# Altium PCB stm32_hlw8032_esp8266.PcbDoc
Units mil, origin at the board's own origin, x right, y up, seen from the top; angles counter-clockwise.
Board outline 3320.87 x 3460.63 mil, 2 copper layers (Top Layer, Bottom Layer); 68 components, 53 nets, 223 pads, 57 vias.
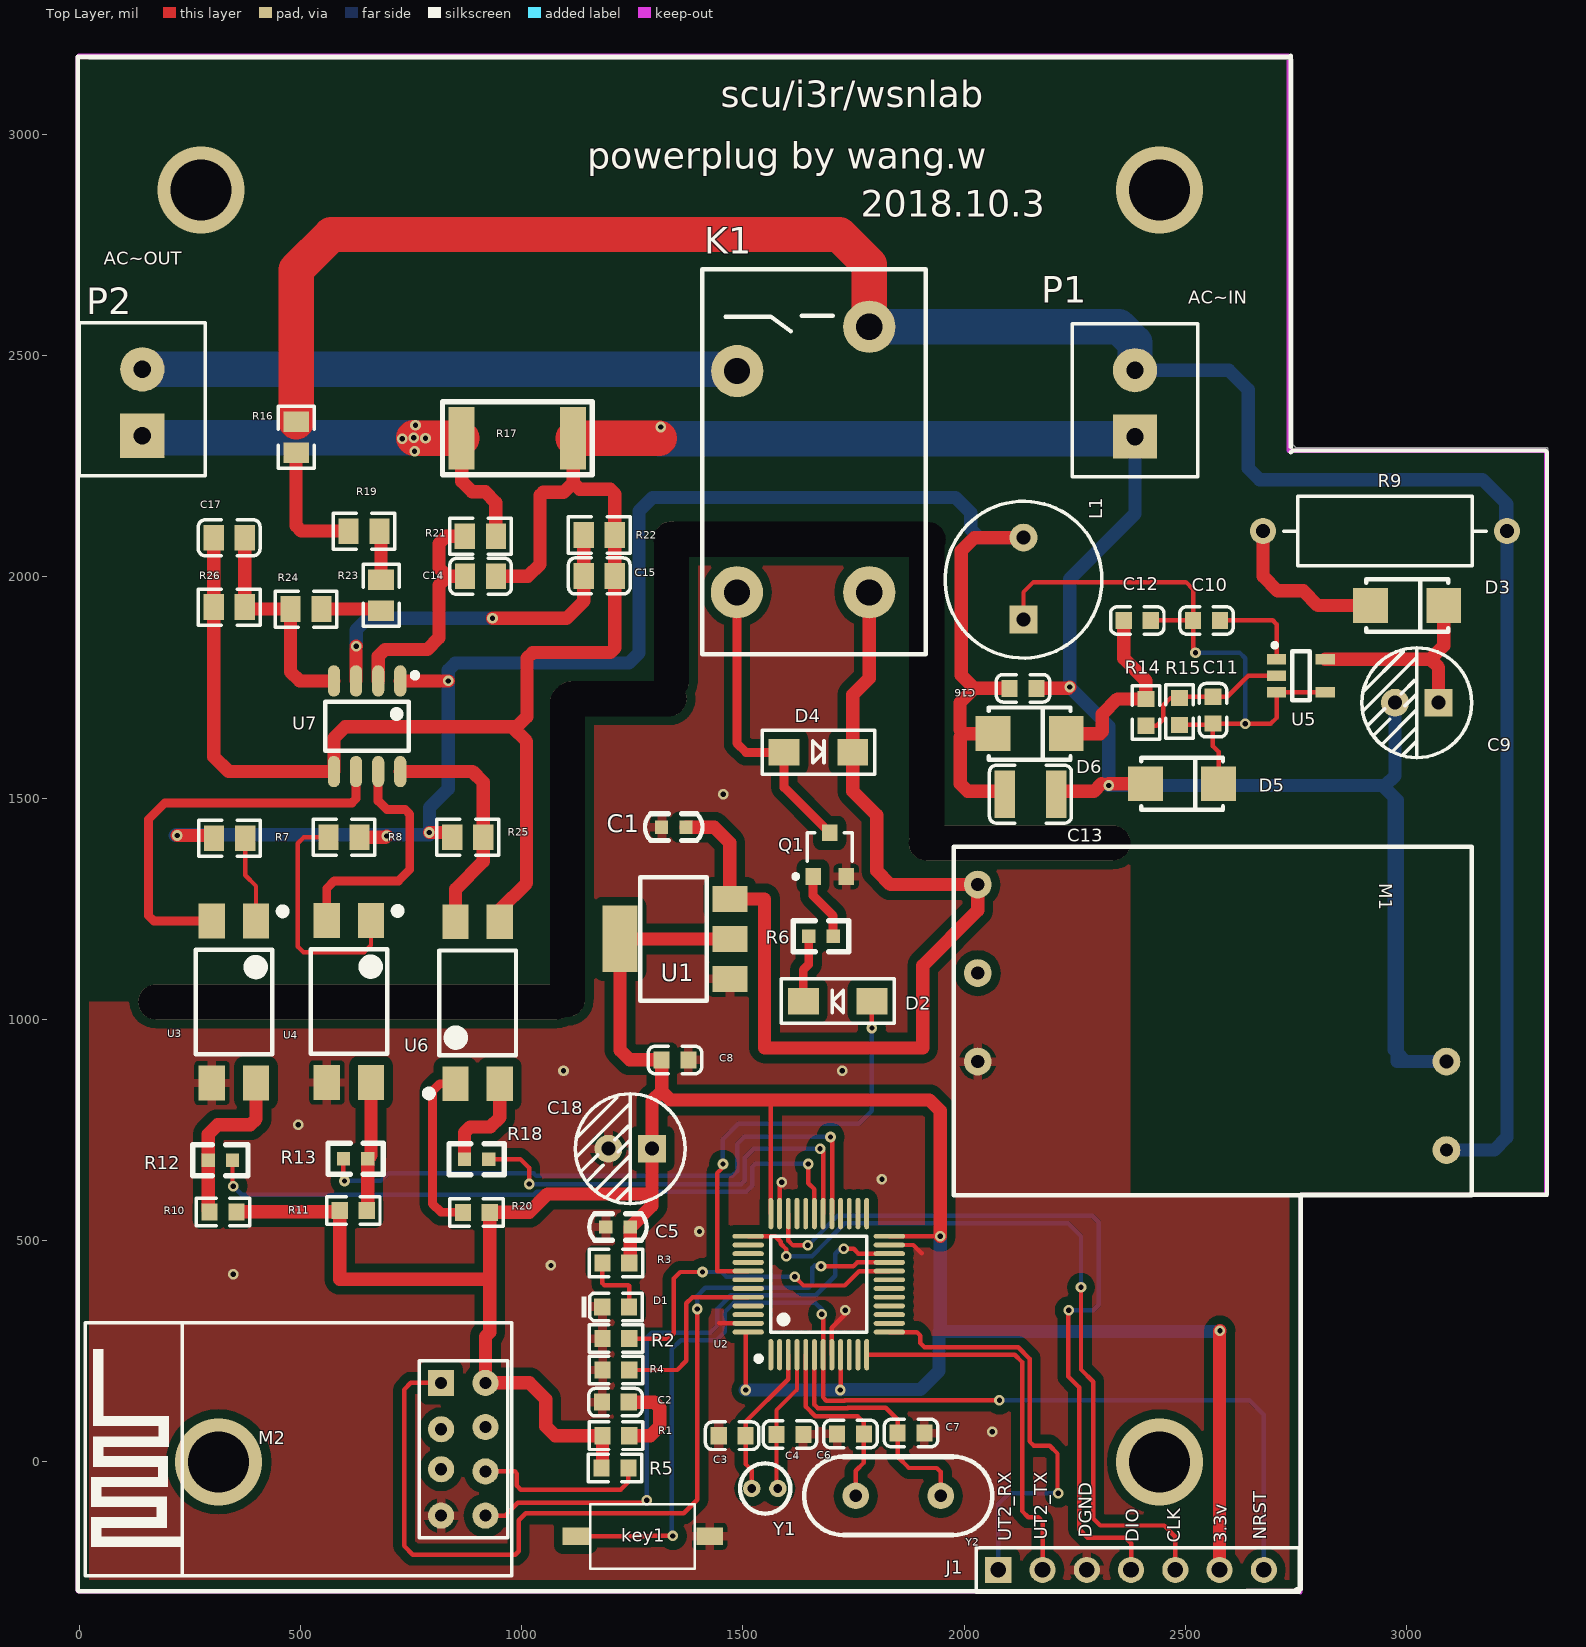
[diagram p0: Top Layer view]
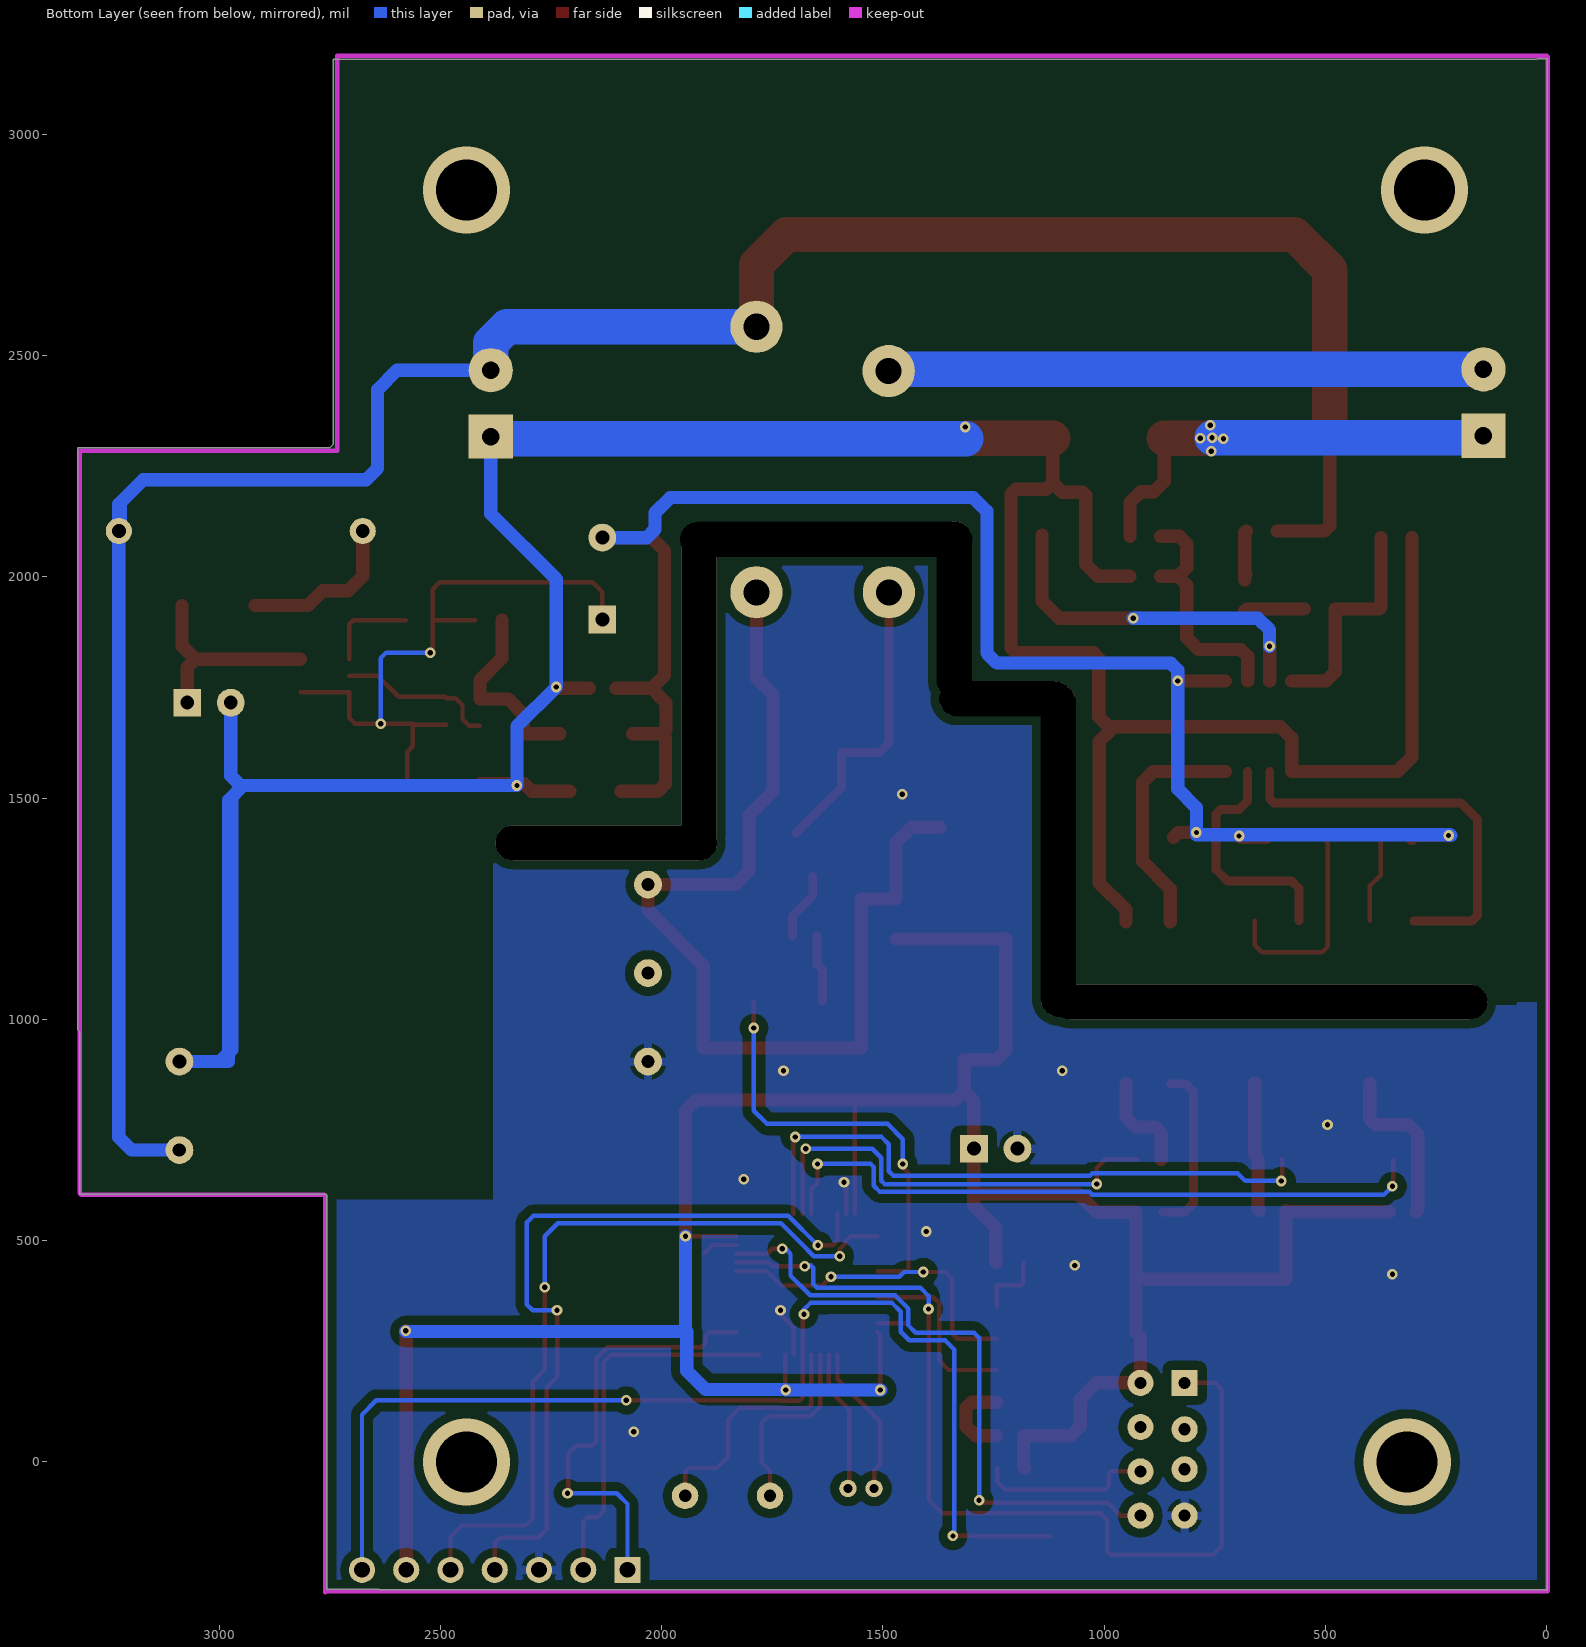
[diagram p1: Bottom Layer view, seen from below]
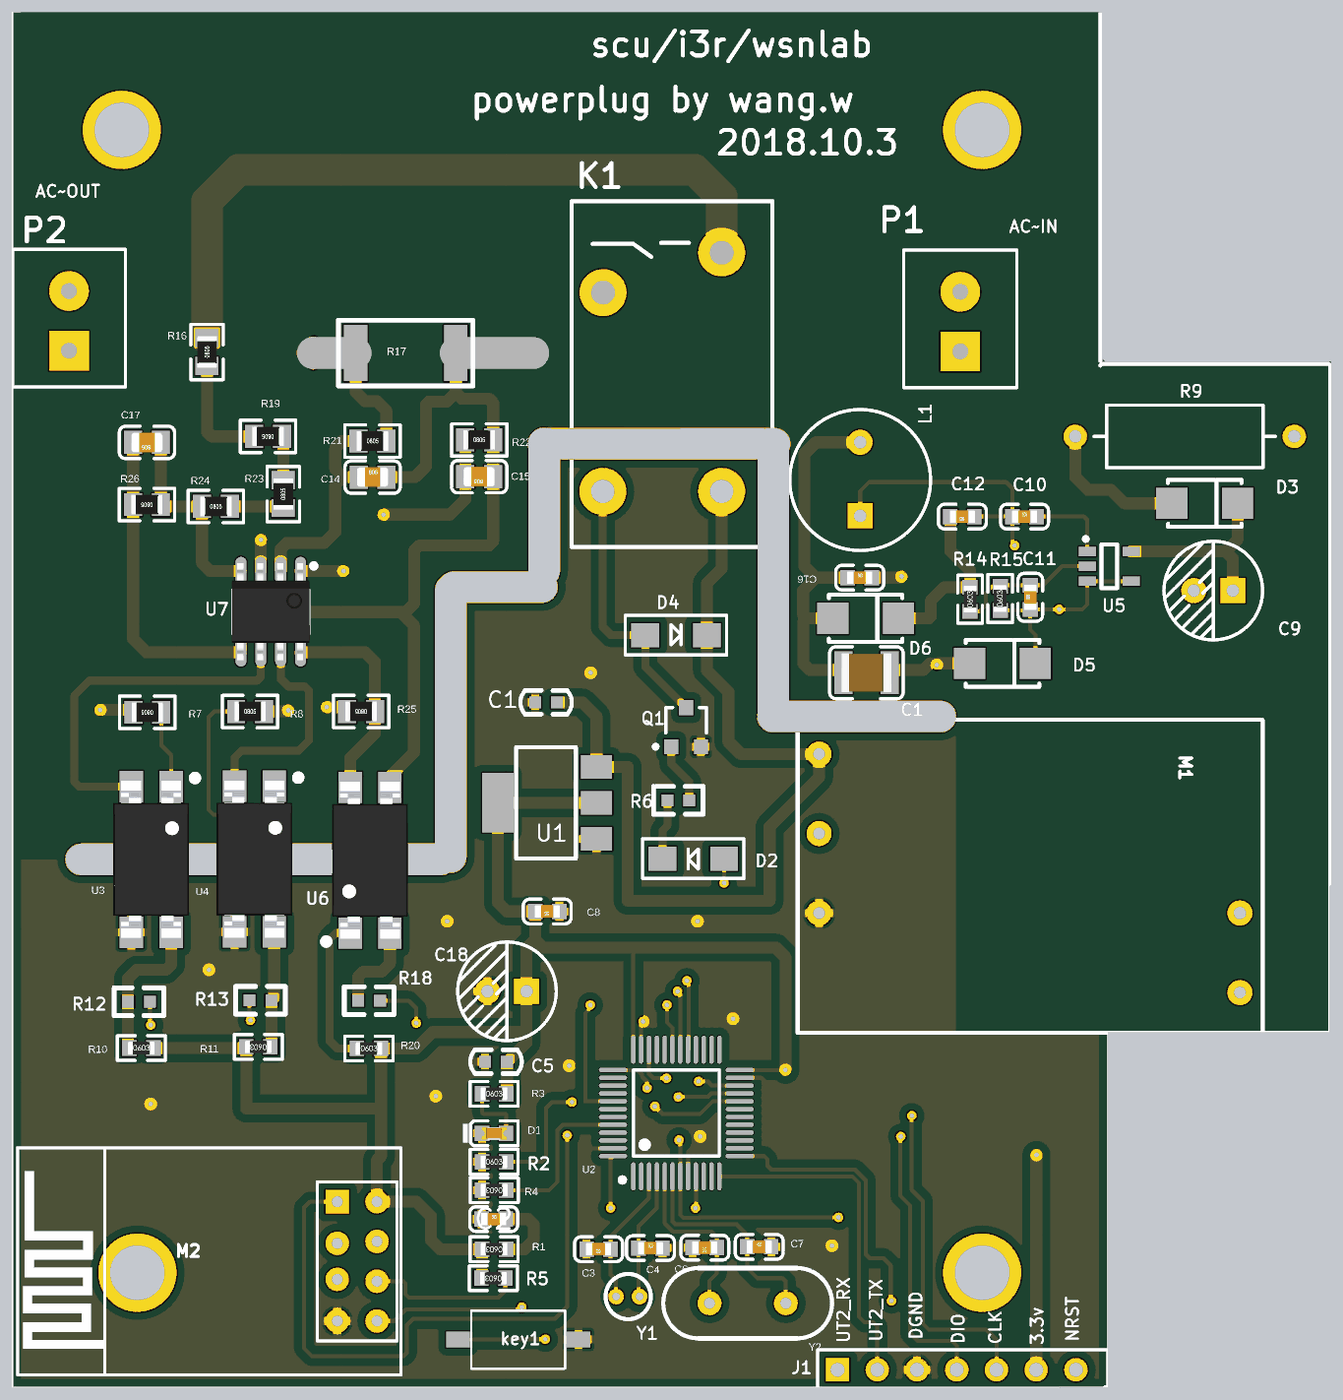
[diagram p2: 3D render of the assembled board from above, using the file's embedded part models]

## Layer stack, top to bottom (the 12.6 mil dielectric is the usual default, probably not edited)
Top Solder: solder mask 0.4, Solder Resist, Dk 3.5
Top Layer: signal copper 1.4
Dielectric 1: dielectric 12.6, FR-4, Dk 4.8
Bottom Layer: signal copper 1.4
Bottom Solder: solder mask 0.4, Solder Resist, Dk 3.5

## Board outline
22.64,3169.29 2742.13,3169.29 2742.13,2299.21 2750,2291.34 3318.9,2291.34 3318.9,976.38 3314.96,972.44 3314.96,604.33 2757.87,604.33 2756.89,603.35 2756.89,-288.39 2637.8,-288.39 2636.81,-289.37 -0.98,-289.37 -0.98,3170.28 -1.97,3171.26 20.67,3171.26

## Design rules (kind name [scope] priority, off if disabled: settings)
Clearance Clearance_1 [InPolygon] p1: gap=20 ignorepadtopadclearanceinfootprint=FALSE except(0: Arc-Hole Track-Hole SMDPad-Hole THPad-Hole Via-Hole Fill-Hole Poly-Hole Region-Hole Text-Hole)
Clearance [All] p2: gap=7 ignorepadtopadclearanceinfootprint=FALSE except(0: Arc-Hole Track-Hole SMDPad-Hole THPad-Hole Via-Hole Fill-Hole Poly-Hole Region-Hole Text-Hole)
ComponentClearance [All] p1: gap=4 collisioncheckmode=3 verticalgap=4 showdistances=FALSE
DiffPairsRouting [All] p1: maxlimit=10 minlimit=10 mostfreqgap=10 toplayer_minwidth=10 toplayer_maxwidth=15 toplayer_prefwidth=15 bottomlayer_minwidth=10 bottomlayer_maxwidth=15 bottomlayer_prefwidth=15 maxuncoupledlength=500
HoleSize [All] p1: absolutevalues=TRUE maxlimit=500 minlimit=1 maxpercent=80.000 minpercent=20.000
HoleToHoleClearance [All] p1: gap=4 allowstackedmicrovias=TRUE
MinimumSolderMaskSliver [All] p1: minsoldermaskwidth=4
PolygonConnect PolygonConnect_1 [Isvia] p1: connectstyle=Direct reliefconductorwidth=10 reliefentries=4 polygonreliefangle="90 Angle" airgapwidth=10
PolygonConnect [All] p2: connectstyle=Relief reliefconductorwidth=20 reliefentries=4 polygonreliefangle="90 Angle" airgapwidth=10
RoutingVias [All] p1: holewidth=20 width=30 viastyle="Through Hole" minholewidth=10 minwidth=10 maxholewidth=28 maxwidth=50
SilkToSilkClearance [All] p1: silktosilkclearance=4
SilkToSolderMaskClearance [IsPad] p1: minsilkscreentomaskgap=0 clearancetoexposedcopper=TRUE
SolderMaskExpansion [All] p1: expansion=4
Width [All] p1: maxlimit=500 minlimit=10 preferedwidth=10 minimp=50.000000 maximp=50.000000 favimp=50.000000
23 further rules are at their usual default settings.

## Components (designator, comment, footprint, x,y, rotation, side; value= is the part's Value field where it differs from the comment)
C1 "104" 0603C 1349.41,1433.07 r0 top
C2 "0.1μF" LC-0603_C 1211.61,134.84 r0 top
C3 "6pF" LC-0603_C 1475.59,59.06 r180 top
C4 "6pF" LC-0603_C 1606.1,62.01 r0 top
C5 "104" 0603C 1223.43,529.53 r0 top
C6 "20pF" LC-0603_C 1742.91,62.99 r180 top
C7 "20pF" LC-0603_C 1879.72,64.96 r0 top
C8 "0.1μF" LC-0603_C 1346.46,908.46 r180 top
C9 "3.3μF/400V" CAP-ELECT-TH-6.3X7 3022.64,1715.55 r180 top value=2.2μF/400V
C10 "2.2μF/10V" LC-0603_C 2547.44,1901.57 r0 top value="100nF (104) ±10% 50V"
C11 "470pF" LC-0603_C 2562.01,1698.62 r90 top value="100nF (104) ±10% 50V"
C12 "220nF" LC-0603_C 2390.94,1901.57 r180 top value="100nF (104) ±10% 50V"
C13 "100μF" LC-1210_C 2149.61,1508.86 r180 top value="100nF (104) ±10% 50V"
C14 "33nF" LC-0805_C 906.89,2000.98 r0 top value="100nF (104) ±10% 50V"
C15 "33nF" LC-0805_C 1175.2,2001.97 r180 top value="100nF (104) ±10% 50V"
C16 "0.1μF" LC-0603_C 2132.87,1748.03 r0 top value="100nF (104) ±10% 50V"
C17 "33nF" LC-0805_C 338.98,2088.19 r180 top value="100nF (104) ±10% 50V"
C18 "1000μF/400V" CAP-ELECT-TH-6.3X7 1245.08,707.68 r180 top value=2.2μF/400V
D1 "POWER" LC-0603_LED_S1 1212.4,350.39 r0 top value=红色
D2 "IN4148" 1206D 1841.34,1071.34 r270 top
D3 "1N4007" LC-SMA(DO-214AC)_S1 3000.98,1935.04 r180 top
D4 "" 1206D 1543.03,1573.35 r90 top
D5 "US1J(600V 1A)" LC-SMA(DO-214AC)_S1 2492.13,1532.48 r180 top
D6 "1N4007" LC-SMA(DO-214AC)_S1 2147.64,1645.67 r180 top
J1 "4P/NC" HDR1X7 2076.97,-244.09 r0 top
K1 "Relay-5V" SJ-S-105LMH 1683.07,1964.96 r90 top
key1 "SW" KEY-2 1424.61,-168.33 r180 top
L1 "1mH" L-10X14 2133.86,1993.54 r90 top
M1 "ACDC_THX208based" ACDC_THX208 3146.65,605.31 r180 top
M2 "ESP-01&01S Module" "ESP-01&01S Module" 867.91,28.54 r90 top
P1 "Header" 3.81-2P 2386.81,2316.93 r90 top
P2 "Header" 3.81-2P 143.7,2318.9 r90 top
Q1 "S8050" SOT-23 1695.86,1372.05 r0 top
R1 "10KΩ" LC-0603_R 1212.6,59.06 r180 top
R2 "10KΩ" LC-0603_R 1212.6,278.54 r0 top
R3 "1.5KΩ" LC-0603_R 1212.6,449.8 r0 top
R4 "10KΩ" LC-0603_R 1212.8,207.68 r180 top
R5 "4.7KΩ" LC-0603_R 1210.83,-13.78 r180 top
R6 "Res2" 0603 1703.74,1187.99 r180 top value=4.7K
R7 "1KΩ,1%" LC-0805_R 339.96,1409.45 r180 top
R8 "1KΩ,1%" LC-0805_R 598.43,1411.42 r0 top
R9 "39Ω/1W" R-1W-THT 2950.79,2103.35 r180 top
R10 "2.2KΩ" LC-0603_R 325,564.96 r0 top
R11 "2.2KΩ" LC-0603_R 619.29,567.91 r180 top
R12 "0Ω/1W" 0603 291.34,681.5 r0 top
R13 "0Ω/1W" 0603 652.17,685.04 r180 top
R14 "5.49KΩ" LC-0603_R 2410.43,1693.7 r90 top
R15 "4.99KΩ" LC-0603_R 2486.22,1695.67 r90 top
R16 "470KΩ,1%" LC-0805_R 490.16,2315.55 r90 top
R17 "2mΩ/25A" R2512 990.16,2312.99 r0 top
R18 "0Ω/1W" 0603 925.47,684.06 r180 top
R19 "470KΩ,1%" LC-0805_R 643.7,2103.35 r180 top
R20 "2.2KΩ" LC-0603_R 897.64,563.98 r0 top
R21 "1KΩ,1%" LC-0805_R 906.5,2091.54 r0 top
R22 "1KΩ,1%" LC-0805_R 1175.2,2094.49 r0 top
R23 "470KΩ,1%" LC-0805_R 682.09,1958.27 r90 top
R24 "470KΩ,1%" LC-0805_R 512.4,1927.17 r0 top
R25 "1KΩ,1%" LC-0805_R 877.95,1411.42 r180 top
R26 "1KΩ,1%" LC-0805_R 338.98,1931.69 r180 top
U1 "LM1117-3.3V" SOT-223/P2.3 1359.25,1180.12 r180 top
U2 "STM32F103C8T6" LC-LQFP-48_7x7x05P 1671.26,401.57 r0 top
U3 "PC817" LC-SMD-4 349.61,1039.37 r270 top
U4 "PC817" LC-SMD-4 609.45,1040.35 r270 top
U5 "MP150" LC-SOT-23-5 2760.83,1776.58 r180 top
U6 "PC817" LC-SMD-4 900.39,1037.4 r90 top
U7 "HLW8032" LC-SOP-8_150mil 650.59,1662.4 r180 top
Y1 "32.768K" CRYSTAL 1528.74,-60.04 r180 top
Y2 "8M" 49/U_N 1754.85,-76.77 r0 top value="25MHz ±20ppm 20pF"

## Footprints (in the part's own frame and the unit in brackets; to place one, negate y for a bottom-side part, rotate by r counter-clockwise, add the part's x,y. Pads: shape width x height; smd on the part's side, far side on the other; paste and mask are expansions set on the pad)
3.81-2P [mil]
  rect 100x100 hole 39.37: 1(0,0.99)
  round 100 hole 39.37: 2(150,1)
  silkscreen extent -91,-141 255,143
49/U_N [mil]
  round 60 hole 28: 1(0,0) 2(192,0)
  silkscreen extent -116,-88 308,89, body extent -117,-88 309,89, height 512
0603 [mil]
  rect 30x30 smd: 1(0,0) 2(55,0)
  silkscreen extent -35,-35 90,35
0603C [mil]
  rect 30x30 smd: 1(21.61,1.26) 2(-33.39,1.26)
  silkscreen extent -71,-29 59,31
1206D [mil]
  rect 60x70 smd: 1(30,-50) 2(30,-205)
  silkscreen extent -20,-255 80,0
ACDC_THX208 [mm]
  round 1.6 hole 0.762: 1(1.45,-2.52) 3(28.35,-7.6) 4(28.35,-12.68) 5(28.35,-17.76)
  round 1.6 hole 0.8: 2(1.45,-7.6)
  silkscreen extent 0,-19.94 29.72,0.06
CAP-ELECT-TH-6.3X7 [mm]
  rect 1.6x1.6 hole 0.8: 1(-1.25,0)
  round 1.6 hole 0.8: 2(1.25,0)
  silkscreen extent -3.15,-3.15 3.15,3.15
CRYSTAL [mm]
  round 1 hole 0.5: 1(-1.27,0) 2(0.23,0)
  silkscreen extent -1.99,-1.44 0.9,1.44
"ESP-01&01S Module" [mm]
  rect 1.5x1.5 hole 0.7: 1(3.81,1.27)
  round 1.5 hole 0.7: 2(1.15,1.27) 3(-1.15,1.27) 4(-3.81,1.27) 5(3.81,-1.27) 6(1.27,-1.27) 7(-1.27,-1.27) 8(-3.81,-1.27)
  silkscreen extent -7.25,-2.79 7.25,21.71
HDR1X7 [mm]
  rect 1.5x1.5 hole 0.9: 1(0,0)
  round 1.5 hole 0.9: 2(2.54,0) 3(5.08,0) 4(7.62,0) 5(10.16,0) 6(12.7,0) 7(15.24,0)
  silkscreen extent -1.27,-1.27 17.27,1.27
KEY-2 [mm]
  rect 1.5x1 smd: 1(-0.005,-0.001) 2(7.685,-0.001)
  silkscreen extent 0.85,-1.85 6.85,1.86
L-10X14 [mm]
  rect 1.6x1.6 hole 0.8: 1(-2.286,0)
  round 1.6 hole 0.8: 2(2.413,0)
  silkscreen extent -4.5,-4.5 4.5,4.5
LC-0603_C [mm]
  rect 0.93x0.98 smd: 1(-0.77,0) 2(0.77,0)
  silkscreen extent -1.53,-0.79 1.54,0.79, body extent -0.8,-0.4 0.8,0.4, height 0.3
LC-0603_LED_S1 [mm]
  rect 0.93x0.98 smd: A(0.77,0) K(-0.77,0)
  silkscreen extent -1.98,-0.79 1.53,0.79, body extent -0.8,-0.4 0.8,0.4, height 0.6
LC-0603_R [mm]
  rect 0.93x0.98 smd: 1(-0.77,0) 2(0.77,0)
  silkscreen extent -1.54,-0.79 1.53,0.79, body extent -0.85,-0.4 0.85,0.4, height 0.56
LC-0805_C [mm]
  rect 1.16x1.47 smd: 1(-0.89,0) 2(0.89,0)
  silkscreen extent -1.77,-1.04 1.77,1.04, body extent -1,-0.62 1,0.63, height 0.77
LC-0805_R [mm]
  rect 1.16x1.47 smd: 1(-0.89,0) 2(0.89,0)
  silkscreen extent -1.77,-1.03 1.77,1.04, body extent -1,-0.62 1,0.63, height 0.49
LC-1210_C [mm]
  rect 1.16x2.72 smd: 1(-1.475,0) 2(1.475,0)
  silkscreen extent -2.36,-1.66 2.35,1.66, body extent -1.6,-1.25 1.6,1.25, height 1.3
LC-LQFP-48_7x7x05P [mm]
  oval 0.28x1.8 smd mask+0.051: 1(-2.75,-4.05) 2(-2.25,-4.05) 3(-1.75,-4.05) 4(-1.25,-4.05) 5(-0.75,-4.05) 6(-0.25,-4.05) 7(0.25,-4.05) 8(0.75,-4.05) 9(1.25,-4.05) 10(1.75,-4.05) 11(2.25,-4.05) 12(2.75,-4.05) 25(2.75,4.05) 26(2.25,4.05) 27(1.75,4.05) 28(1.25,4.05) 29(0.75,4.05) 30(0.25,4.05) 31(-0.25,4.05) 32(-0.75,4.05) 33(-1.25,4.05) 34(-1.75,4.05) 35(-2.25,4.05) 36(-2.75,4.05)
  oval 1.8x0.28 smd mask+0.051: 13(4.05,-2.75) 14(4.05,-2.25) 15(4.05,-1.75) 16(4.05,-1.25) 17(4.05,-0.75) 18(4.05,-0.25) 19(4.05,0.25) 20(4.05,0.75) 21(4.05,1.25) 22(4.05,1.75) 23(4.05,2.25) 24(4.05,2.75) 37(-4.05,2.75) 38(-4.05,2.25) 39(-4.05,1.75) 40(-4.05,1.25) 41(-4.05,0.75) 42(-4.05,0.25) 43(-4.05,-0.25) 44(-4.05,-0.75) 45(-4.05,-1.25) 46(-4.05,-1.75) 47(-4.05,-2.25) 48(-4.05,-2.75)
  silkscreen extent -3.6,-4.42 2.75,2.75
LC-SMA(DO-214AC)_S1 [mm]
  rect 2x2 smd: 1(2.1,0) 2(-2.1,0)
  silkscreen extent -2.35,-1.5 2.35,1.5
LC-SMD-4 [mm]
  rect 2x1.5 smd: 1(-4.65,1.27) 2(-4.65,-1.27) 3(4.65,-1.27) 4(4.65,1.27)
  silkscreen extent -5.4,-2.2 3,3, body extent -5.02,-2.42 5.01,2.42, height 3.9
LC-SOP-8_150mil [mm]
  oval 0.7x1.8 smd: 1(-1.905,-2.6) 2(-0.635,-2.6) 3(0.635,-2.6) 4(1.905,-2.6) 5(1.905,2.6) 6(0.635,2.6) 7(-0.635,2.6) 8(-1.905,2.6)
  silkscreen extent -2.9,-3.07 2.4,1.4, body extent -2.5,-3.1 2.5,3.1, height 1.75
LC-SOT-23-5 [mm]
  rect 1.1x0.6 smd: 1(1.4,-0.95) 2(1.4,0) 3(1.4,0.95) 4(-1.4,0.95) 5(-1.4,-0.95)
  silkscreen extent -0.5,-1.87 1.62,1.4
R2512 [mm]
  rect 1.5x3.6 smd: 1(-3.2,0) 2(3.2,0)
  silkscreen extent -4.3,-2.1 4.3,2.1
R-1W-THT [mm]
  round 1.5 / inner oval 1.5x2 / far side round 1.5 hole 0.8: 1(-7,0)
  round 1.5 hole 0.8: 2(7,0)
  silkscreen extent -5.8,-2 5.8,2
SJ-S-105LMH [mm]
  round 3 hole 1.5: 1(0,5) 2(0,-2.6) 3(12.7,4.984) 4(15.24,-2.6)
  silkscreen extent -3.56,-5.84 18.54,6.98
SOT-23 [mm]
  rect 0.9x0.95 smd: 1(-0.95,-1.25) 2(0.95,-1.25) 3(0,1.25)
  silkscreen extent -2.07,-1.37 1.3,1.25
SOT-223/P2.3 [mil]
  rect 79x59 smd: 1(-111,89.1) 2(-111,-1.45) 3(-111,-92)
  rect 79x150 smd: 2(137,-1.9)
  silkscreen extent -59,-141 91,139

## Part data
C1 C5: library part CAP, "Capacitor"
C2 C3 C4 C6 C7 C8: library part Cap, "贴片电容"
C9 C18: library part "Cap Pol1", "直插电解电容"
C10 C11 C12 C13 C14 C15 C16 C17: library part CAP, "贴片电容"
D1: library part LED1, "发光二极管"
D2 D4: library part Diode, "Default Diode", PackageDocument=Sep-1996
D3 D5 D6: library part "Diode 1N5408", "贴片二极管"
J1: library part "Header 7", "接口"
K1: library part SJ-S-105LMH, "Single-Pole Dual-Throw Relay"
key1: "Switch"
L1: library part IND_8, "直插绕线电感"
M1: library part ACDC, "THX208Based"
P1 P2: library part "Header 2", "Header, 2-Pin"
Q1: library part NPN, "NPN Bipolar Transistor"
R1 R2 R3 R4 R7 R8 R9 R10 R11 R12 R13 R14 R15 R16 R17 R18 R19 R20 R21 R22 R23 R24 R25 R26: library part 电阻, "贴片电阻"
R5: library part "0805 62KΩ (6202) 1%", "贴片电阻", Package=0402, SuppliersPartNumber=C17783
R6: "Resistor"
U1: library part 1117
U2: library part STM32F103CBT6, "IC"
U3 U4 U6: library part PS2501L-1-F3-A, "IC"
U5 U7: "IC"
Y1: library part XTAL, "Crystal Oscillator"
Y2: library part XTAL_1, "晶振（直插）"

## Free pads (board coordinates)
  oval 984.25x78.74 hole 78.74 slot 984.25 at 0 deg paste+0: 0(625.98,1039.37)
  oval 78.74x750 hole 78.74 slot 750 at 90 deg paste+0: 0(1103.35,1380.91) 0(1915.35,1748.03)
  oval 300x78.74 hole 78.74 slot 300 at 0 deg paste+0: 0(1222.44,1724.41)
  oval 78.74x400 hole 78.74 slot 400 at 90 deg paste+0: 0(1338.58,1925.2)
  oval 600x78.74 hole 78.74 slot 660 at 0 deg paste+0: 0(1627.95,2084.65)
  oval 500x78.74 hole 78.74 slot 500 at 0 deg paste+0: 0(2125,1398.62)

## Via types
v1: diameter 24, hole 12, Top Layer to Bottom Layer, 53 vias
v2: diameter 196.85, hole 137.8, Top Layer to Bottom Layer, 4 vias

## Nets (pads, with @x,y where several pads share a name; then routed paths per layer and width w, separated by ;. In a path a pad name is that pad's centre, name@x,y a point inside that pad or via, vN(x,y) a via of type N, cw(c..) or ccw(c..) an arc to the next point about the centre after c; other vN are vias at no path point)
+3.3V: C5.1 C8.2 C18.1 J1.6 M2.5 R1.2 R3.2 R5.2 R10.2 R11.2 R20.2 U1.2 U2.9 U2.24 U2.36 U2.48 | length 6476.4
  Top Layer w10: v1(1505.91,162.4) 1505.91,287.4 U2.48 ; U2.36 1562.99,813.98 1566.93,817.91 ; v1(1719.49,162.4) 1720.47,163.38 U2.9 ; U2.24 v1(1945.87,509.84)
  Top Layer w30: R10.2 586.02,564.96 R11.2 588.98,412.99 927.56,412.99 927.95,413.39 ; R5.2@1178.54,-14.76 1182.28,-11.02 R1.2 1075.79,59.06 1054.13,80.71 1054.13,141.73 1017.32,178.54 M2.5 917.91,283.07 927.95,293.11 927.95,413.39 ; R3.2 1245.04,451.93 C5.1 1246.33,530.79 1294.29,578.74 1294.29,610.24 ; U1.2@1470.25,1181.57 1222.7,1181.57 1222.25,1182.02 1222.25,930.31 1244.09,908.47 C8.2 1316.14,837.4 ; v1(1945.87,509.84) 1945.87,793.31 1921.26,817.91 1566.93,817.91 1335.63,817.91 1316.14,837.4 ; J1.6 2576.97,295.47 v1(2577.76,296.26) ; 927.95,413.39 R20.2 1016.73,563.98 1058.07,605.32 1289.37,605.32 1294.29,610.24 ; 1294.29,610.24 C18.1 1294.29,815.55 1316.14,837.4
  Bottom Layer w30: v1@1504.92,162.4 v1(1505.91,162.4) v1(1719.49,162.4) ; v1@1719.49,163.39 1900.59,163.39 1943.11,205.91 1943.11,294.49 ; v1(1945.87,509.84) 1945.87,297.24 1943.11,294.49 ; v1@2577.76,294.49 1943.11,294.49
+5V: C1.1 D4.2 K1.2 M1.5 U1.3 | length 2342.1
  Top Layer w30: C1.1 1434.76,1434.33 1470.25,1398.84 U1.3 1548.75,1272.12 1548.75,935.5 1905.96,935.5 1905.96,1121.6 2030.51,1246.15 M1.5 1833.27,1304.53 1802.17,1335.63 1802.17,1461.61 1748.03,1515.75 D4.2 1748.03,1733.27 1785.43,1770.67 K1.2
A+5V: C13.2 C16.1 D6.1 L1.2 R7.2 R8.2 R25.2 U7.1 | length 3957.2
  Top Layer w30: v1(221.46,1415.35) 299.02,1415.35 R7.2 ; R8.2 691.93,1411.42 v1(694.88,1414.37) ; U7.1 v1(833.66,1764.76) ; v1(791.34,1422.24) 832.09,1422.24 R25.2 ; D6.1 1999.01,1645.67 ; C13.2@2091.54,1515.75 2007.87,1515.75 1991.14,1532.48 1991.14,1637.8 1999.01,1645.67 ; C16.1 2022.64,1748.03 ; L1.2 2022.6,2088.54 1993.11,2059.06 1993.11,1777.56 2022.64,1748.03 ; 1999.01,1645.67 1990.16,1654.53 1990.16,1715.55 2022.64,1748.03
  Bottom Layer w30: v1(221.46,1415.35) 216.54,1415.35 218.5,1417.32 791.34,1417.32 v1(791.34,1422.24) 791.34,1478.35 833.66,1520.67 v1(833.66,1764.76) 833.66,1789.37 849.41,1805.12 1242.13,1805.12 1264.76,1827.76 1264.76,2148.62 1295.28,2179.13 1980.31,2179.13 2014.76,2144.69 2014.76,2107.28 2033.5,2088.54 L1.2
AC220V-L: K1.4 M1.1 P1.2 R9.1 R16.2 | length 5241.5
  Top Layer w80: R16.2 490.16,2693.9 569.88,2773.62 1717.52,2773.62 1785.43,2705.71 K1.4
  Bottom Layer w30: P1.2 2598.03,2466.93 2641.73,2423.23 2641.73,2245.08 2667.32,2219.49 3171.26,2219.49 3223.42,2167.32 ; M1.1 3197.64,704.53 3226.38,733.27 R9.1 3226.38,2164.37 3223.42,2167.32 ; R9.1@3223.42,2093.5 3223.42,2167.32
  Bottom Layer w80: K1.4 2349.41,2564.96 2385.81,2528.56 P1.2
AC220V-N: C9.2 C13.1 C14.2 C15.1 C16.2 C17.2 D5.1 M1.2 P1.1 R17.2 R22.2 R26.2 U6.3 U7.5 | length 7627.9
  Top Layer w30: C17.2 R26.2 303.94,1593.7 337.6,1560.04 U7.5 575.59,1635.63 601.38,1661.42 977.36,1661.42 ; C14.2 1013.78,2000.98 1041.34,2028.54 1041.34,2184.06 1048.23,2190.94 1094.49,2190.94 1116.14,2212.6 ; U6.3 950.39,1247.64 1010.83,1308.07 1010.83,1627.95 977.36,1661.42 ; R17.2 1116.14,2212.6 ; C16.2 2235.24,1748.03 v1(2238.19,1750.98) ; C13.1@2207.68,1515.75 2293.31,1515.75 2310.04,1532.48 ; v1@2326.77,1532.48 D5.1 ; 977.36,1661.42 989.17,1661.42 1011.81,1684.06 1011.81,1815.94 1024.61,1828.74 1200,1828.74 1210.24,1838.98 C15.1 R22.2 1210.24,2187.4 1199.8,2197.83 1130.91,2197.83 1116.14,2212.6
  Top Layer w80: R17.2 1311.02,2312.99
  Bottom Layer w30: P1.1 2385.83,2142.72 2238.19,1995.08 v1(2238.19,1750.98) 2326.77,1662.4 v1(2326.77,1528.54) 2944.88,1528.54 2978.35,1495.08 2978.35,924.21 ; 2951.77,1528.54 2973.42,1550.19 C9.2 ; 2971.45,1495.08 2971.45,931.11 2978.35,924.21 ; M1.2 2998.03,904.53 ; 2978.35,924.21 2978.35,904.53 2998.03,904.53 ; 2978.35,924.21 2998.03,904.53
  Bottom Layer w80: 1312.01,2312.01 2380.9,2312.01 P1.1
  other v1: 1313.98,2338.58
BOOT0: R4.1 U2.44 | length 412.9
  Top Layer w10: R4.1 1351.38,207.68 1372.05,228.35 1372.05,358.27 1385.83,372.05 U2.44
CTL_Pin: D2.1 U2.41 | length 984.6
  Top Layer w10: v1(1454.72,673.23) 1454.72,665.35 1441.93,652.56 1441.93,431.1 U2.41 ; v1(1791.34,980.32) D2.1
  Bottom Layer w10: v1(1454.72,673.23) 1454.72,729.33 1489.17,763.78 1761.81,763.78 1791.34,793.31 v1(1791.34,980.32)
DGND: C1.2 C2.1 C3.2 C4.2 C5.2 C6.2 C7.2 C8.1 C18.2 D1.K J1.3 key1.1 M1.3 M2.4 Q1.2 R2.1 R4.2 U1.1 U2.8 U2.23 U2.35 U2.47 U3.3 U4.3 | length 332.5
  Top Layer w10: 1445.86,312.99 U2.47 ; U2.35 1582.68,626.97 v1(1587.6,631.89) ; U2.8 1700.79,303.15 1731.3,333.66 v1(1731.3,342.52) ; U2.23 1884.84,490.16 1903.54,471.46
  other v1: 2062.99,67.91 348.43,424.21 1065.94,443.9 1401.57,520.67 1813.98,638.78 495.08,761.81 1094.49,883.86 1724.41,883.86 1455.71,1508.86
NetC2_2: C2.2 R1.1 | length 194.8
  Top Layer w30: C2.2 1299.21,134.84 1312.01,122.05 1312.01,80.71 1290.35,59.06 R1.1
NetC9_1: C9.1 D3.2 U5.5 | length 482.6
  Top Layer w30: U5.5 3053.15,1813.98 ; C9.1@3075.78,1711.61 C9.1 3071.85,1795.28 3053.15,1813.98 ; D3.2 3083.66,1844.49 3053.15,1813.98
NetC10_1: C10.1 C11.1 C12.1 D5.2 L1.1 R15.1 U5.3 U5.4 | length 1503.4
  Top Layer w10: L1.1 2133.86,1965.55 2156.5,1988.19 2500.98,1988.19 2517.13,1972.05 C10.1 ; C12.1 C10.1 ; R15.1 2559.06,1665.35 C11.1 ; v1(2522.64,1828.74) 2517.13,1834.25 C10.1 ; D5.2 2574.8,1604.33 2562.01,1617.13 C11.1 ; U5.4 U5.3 2705.71,1681.1 2692.91,1668.31 v1(2634.84,1668.31) C11.1
  Bottom Layer w10: v1(2522.64,1828.74) 2622.05,1828.74 2634.84,1815.94 v1(2634.84,1668.31)
NetC10_2: C10.2 U5.1 | length 210.4
  Top Layer w10: C10.2 2696.85,1901.57 2705.71,1892.72 U5.1
NetC11_2: C11.2 R14.1 R15.2 U5.2 | length 360.6
  Top Layer w10: R14.1 2435.04,1663.39 2449.8,1678.15 2449.8,1709.65 2466.14,1725.98 R15.2 2489.17,1728.94 C11.2 2594.09,1728.94 2641.73,1776.58 U5.2
NetC12_2: C12.2 D6.2 R14.2 | length 433.8
  Top Layer w30: D6.2 2307.09,1645.67 2312.01,1650.59 2312.01,1689.96 2346.06,1724.02 R14.2 2410.43,1765.75 2360.63,1815.55 C12.2
NetC14_1: C14.1 R21.1 U7.2 | length 544.3
  Top Layer w30: U7.2 675.59,1820.27 690.94,1835.63 786.42,1835.63 812.99,1862.2 812.99,1981.3 832.68,2000.98 ; C14.1 832.68,2000.98 ; R21.1@871.85,2091.14 R21.1 829.72,2091.54 812.99,2074.8 812.99,2020.67 832.68,2000.98
NetC15_2: C15.2 R22.1 U7.3 | length 805.8
  Top Layer w30: U7.3 625.59,1842.91 v1(625.98,1843.31) ; v1(934.06,1906.5) 1101.38,1906.5 1140.16,1945.27 C15.2 R22.1
  Bottom Layer w30: v1(625.98,1843.31) 625.98,1879.92 652.56,1906.5 v1(934.06,1906.5)
NetC17_1: C17.1 R24.1 R26.1 U7.4 | length 510.2
  Top Layer w30: C17.1 R26.1 378.55,1927.17 R24.1 477.36,1785.43 498.03,1764.76 U7.4
NetD1_A: D1.A R3.1 | length 156.5
  Top Layer w10: R3.1 1182.28,403.74 1186.42,399.61 1241.14,399.61 1242.72,398.03 D1.A
NetD2_2: D2.2 R6.2 | length 151.8
  Top Layer w20: D2.2 1636.34,1111.73 1648.74,1124.13 R6.2
NetD3_1: D3.1 R9.2 | length 372.8
  Top Layer w30: R9.2 2675.2,2000.98 2707.68,1968.5 2765.75,1968.5 2799.21,1935.04 D3.1
NetD4_1: D4.1 K1.1 Q1.3 | length 681
  Top Layer w20: K1.1 1486.22,1624.02 1506.89,1603.35 D4.1 1593.03,1524.09 Q1.3
NetK1_3: K1.3 P2.2 | length 1340.6
  Bottom Layer w80: P2.2@146.64,2468.9 K1.3@1487.2,2468.9
NetM2_7: M2.7 R5.1 | length 395.5
  Top Layer w10: M2.7 984.25,-21.46 989.17,-26.38 989.17,-54.13 998.03,-62.99 1223.43,-62.99 1241.14,-45.28 R5.1
NetP2_1: P2.1 R17.1 R21.2 | length 994.7
  Top Layer w30: R17.1 864.17,2215.55 887.8,2191.93 917.32,2191.93 941.54,2167.72 R21.2
  Top Layer w80: v1(755.91,2313.98) 756.89,2312.99 v1(782.48,2312.99) R17.1
  Bottom Layer w80: P2.1 147.64,2313.98 v1(755.91,2313.98)
  other v1: 757.87,2283.46 730.31,2312.01 759.84,2342.52
NetQ1_1: Q1.1 R6.1 | length 153.6
  Top Layer w20: Q1.1 1658.46,1279.53 1703.74,1234.25 R6.1
NetR2_2: R2.2 U2.20 | length 748.9
  Top Layer w10: R2.2 1331.69,278.54 1343.5,290.35 1343.5,414.37 1358.27,429.13 v1(1408.46,429.13) ; v1(1617.13,418.31) 1636.81,398.62 1730.23,398.62 1762.71,431.1 U2.20
  Bottom Layer w10: v1(1408.46,429.13) 1451.77,429.13 1462.6,418.31 v1(1617.13,418.31)
NetR7_1: R7.1 U3.1 | length 197.2
  Top Layer w10: R7.1 375,1325.79 399.61,1301.18 U3.1
NetR8_1: R8.1 U4.1 | length 541.5
  Top Layer w10: R8.1 507.87,1411.42 494.09,1397.64 494.09,1164.37 506.89,1151.57 643.7,1151.57 659.45,1167.32 U4.1
NetR10_1: R10.1 R12.1 U3.4 | length 380.8
  Top Layer w30: R10.1 291.34,568.31 R12.1 291.34,740.16 312.99,761.81 386.81,761.81 399.61,774.61 U3.4
NetR11_1: R11.1 R13.1 U4.4 | length 293.4
  Top Layer w30: R11.1 652.17,570.47 R13.1 659.45,692.32 U4.4
NetR16_1: R16.1 R19.2 | length 288.8
  Top Layer w30: R16.1 490.16,2115.16 501.97,2103.35 R19.2
NetR18_2: R18.2 U6.2 | length 229.9
  Top Layer w30: R18.2 870.47,743.5 883.86,756.89 929.13,756.89 950.39,778.15 U6.2
NetR19_1: R19.1 R23.2 | length 114.2
  Top Layer w30: R19.1 682.09,2100 R23.2 ; R23.2@680.12,2004.53 R23.2@682.09,2002.56
NetR20_1: R20.1 U6.1 | length 390.3
  Top Layer w20: U6.1 814.96,854.33 798.23,837.6 798.23,583.66 817.91,563.98 R20.1
NetR23_1: R23.1 R24.2 | length 136.3
  Top Layer w30: R24.2 678.15,1927.17 R23.1
NRST: J1.7 key1.2 U2.7 | length 2622.3
  Top Layer w10: key1.2 1287.4,-168.31 1288.39,-167.32 v1(1341.54,-167.32) ; v1(1678.15,333.66) 1681.1,330.71 U2.7 1681.1,145.67 1688.37,138.4 1729.43,138.4 1730.07,139.05 v1(2079.46,139.05)
  Bottom Layer w10: v1(1341.54,-167.32) 1338.58,-164.37 1338.58,253.94 1359.25,274.61 1439.96,274.61 1459.15,293.8 1459.15,339.07 1479.33,359.25 1587.27,359.25 ; 1587.3,359.22 1626.86,359.22 ; 1626.89,359.25 1663.39,359.25 1679.13,343.5 1678.15,342.52 v1(1678.15,333.66) ; v1(2079.46,139.05) 2644.42,139.05 2676.97,106.5 J1.7
OSC32_IN: C3.1 U2.3 Y1.2 | length 347.8
  Top Layer w10: Y1.2 1519.69,-18.7 1505.91,-4.92 C3.1 1505.91,90.55 1602.36,187.01 U2.3
OSC32_OUT: C4.1 U2.4 Y1.1 | length 322.6
  Top Layer w10: Y1.1 1575.79,-57.09 C4.1 1575.79,117.13 1622.05,163.38 U2.4
OSC_IN: C6.1 U2.5 Y2.1 | length 436.9
  Top Layer w10: U2.5 1641.73,125 1663.39,103.35 1758.86,103.35 1773.23,88.98 C6.1 1773.23,-1.57 1754.85,-19.95 Y2.1
OSC_OUT: C7.1 U2.6 Y2.2 | length 564.8
  Top Layer w10: U2.6 1661.42,129.36 1669.37,121.4 1736.47,121.4 1737.12,122.05 1822.83,122.05 1849.41,95.47 C7.1 1849.41,11.81 1875,-13.78 1937.99,-13.78 1946.85,-22.64 Y2.2
PA8: R13.2 U2.29 | length 1406.7
  Top Layer w10: R13.2 597.17,637.09 v1(599.41,634.84) ; v1(1697.83,734.25) 1702.15,729.94 1702.15,562.39 U2.29
  Bottom Layer w10: v1(599.41,634.84) 681.1,634.84 698.1,651.84 1026.78,651.84 1032.35,646.28 1476,646.28 1486.67,656.94 1486.67,717.97 1502.95,734.25 v1(1697.83,734.25)
PA9: R18.1 U2.30 | length 1006.2
  Top Layer w10: R18.1 997.05,684.06 1016.84,664.26 v1(1016.84,627.84) ; v1(1674.21,707.68) 1681.1,700.79 U2.30
  Bottom Layer w10: v1(1016.84,627.84) 1495.95,627.84 1503.67,635.56 1503.67,687.3 1524.04,707.68 v1(1674.21,707.68)
PA10: R12.2 U2.31 | length 1537.9
  Top Layer w10: R12.2 346.34,625.12 v1(348.43,623.03) ; v1(1647.64,673.23) 1647.64,629.92 1661.42,616.14 U2.31
  Bottom Layer w10: v1(348.43,623.03) 367.61,603.84 1026.78,603.84 1033.78,610.84 1507.5,610.84 1520.67,624.02 1520.67,666.34 1527.56,673.23 v1(1647.64,673.23)
PB10: M2.1 U2.21 | length 2155.2
  Top Layer w10: M2.1 749.41,178.54 734.25,163.39 734.25,-189.96 753.94,-209.65 985.24,-209.65 993.11,-201.77 993.11,-131.89 1008.86,-116.14 1366.14,-116.14 1396.65,-85.63 v1(1396.65,345.47) ; v1(1676.18,441.93) 1749.49,441.93 1758.35,450.79 U2.21
  Bottom Layer w10: v1(1396.65,345.47) 1396.65,375 1414.91,393.25 1648.17,393.25 1656.87,401.95 1656.87,438.37 1662.42,443.92 1664.41,441.93 v1(1676.18,441.93)
PB11: M2.8 U2.22 | length 1433.3
  Top Layer w10: M2.8 962.2,-121.46 991.14,-92.52 1276.57,-92.52 v1(1282.48,-86.61) ; v1(1727.36,481.3) 1750,481.3 1760.83,470.47 U2.22
  Bottom Layer w10: v1(1282.48,-86.61) 1282.48,280.51 1293.8,291.83 1425.69,291.83 1442.15,308.3 1442.15,346.12 1472.29,376.25 1594.31,376.25 ; 1594.34,376.22 1619.81,376.22 ; 1619.84,376.25 1664.13,376.25 1708.66,420.78 1708.66,470.47 1719.49,481.3 v1(1727.36,481.3)
PF: U4.2 U7.7 | length 552.9
  Top Layer w20: U4.2 559.45,1295.67 576.77,1312.99 721.46,1312.99 747.05,1338.58 747.05,1463.58 736.22,1474.41 694.88,1474.41 675.59,1493.7 U7.7
RX: R25.1 U6.4 U7.8 | length 538.7
  Top Layer w30: U7.8 888.78,1560.04 912.99,1535.83 R25.1 912.99,1356.89 850.39,1294.29 U6.4
SWCLK: J1.5 U2.37 | length 1753.1
  Top Layer w10: U2.37 1572.83,509.84 1585.36,497.32 1585.36,492.96 1597.44,480.88 v1(1597.44,464.57) ; v1(2263.78,394.69) 2263.78,208.66 2291.34,181.1 2291.34,-127.95 2307.09,-143.7 2451.77,-143.7 2476.97,-168.9 J1.5
  Bottom Layer w10: v1(1597.44,464.57) 1655.99,464.57 1670.65,479.23 1670.65,479.71 1730.05,539.1 2234.52,539.1 2263.78,509.84 v1(2263.78,394.69)
SWDIO: J1.4 U2.34 | length 1754.9
  Top Layer w10: U2.34 1602.36,500 1613.19,489.17 v1(1646.65,489.17) ; v1@2235.24,341.54 2235.24,192.91 2259.84,168.31 2259.84,-152.56 2278.54,-171.26 2364.17,-171.26 2376.97,-184.06 J1.4
  Bottom Layer w10: v1(1646.65,489.17) 1713.58,556.1 2289.37,556.1 2304.13,541.34 2304.13,355.32 2291.34,342.52 v1(2236.22,342.52)
TX: U3.2 U7.6 | length 915.4
  Top Layer w20: U3.2 168.31,1222.44 156.5,1234.25 156.5,1451.77 193.9,1489.17 616.14,1489.17 625.59,1498.62 U7.6
USART2_RX: J1.1 U2.13 | length 998
  Top Layer w10: U2.13 1892.72,293.31 1900.59,285.43 1900.59,268.7 1910.16,259.13 2121.78,259.13 2147.64,233.27 2147.64,46.26 2157.48,36.42 2192.91,36.42 2210.63,18.7 2210.63,-68.9 v1(2212.6,-70.87)
  Bottom Layer w10: J1.1 2076.97,-95.28 2101.38,-70.87 v1(2212.6,-70.87)
USART2_TX: J1.2 U2.12 | length 860
  Top Layer w10: U2.12 2114.17,242.13 2130.64,225.66 2130.64,-110.95 2144.69,-125 2167.13,-125 2176.97,-134.84 J1.2
VBAT: U2.1
pads on no net: M1.4 M2.2 M2.3 M2.6 U2.2 U2.10 U2.11 U2.14 U2.15 U2.16 U2.17 U2.18 U2.19 U2.25 U2.26 U2.27 U2.28 U2.32 U2.33 U2.38 U2.39 U2.40 U2.42 U2.43 U2.45 U2.46
copper on no net:
  other v2: 314.96,0 2440.94,0 275.59,2874.02 2440.94,2874.02

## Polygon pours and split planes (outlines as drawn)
DGND on Top Layer "Top Layer-No Net 1" (solid, remove dead copper, pour order 16): 6.89,1039.37 1094.49,1039.37 1094.49,1702.76 1118.11,1726.38 1341.54,1726.38 1341.54,2073.82 1349.41,2081.69 1908.46,2081.69 1916.34,2073.82 1916.34,1417.32 2349.41,1417.32 2375,1391.73 2375,605.32 2373.03,603.35 2375,601.38 2759.84,601.38 2759.84,-294.29 2758.86,-295.28 0.98,-295.28 -2.95,-291.34 2.95,-285.43 2.95,1035.43
DGND on Bottom Layer "Top Layer-No Net 1" (solid, remove dead copper, pour order 18): 64.96,1031.5 1089.57,1031.5 1130.91,1072.83 1130.91,1722.44 1324.8,1722.44 1355.31,1752.95 1355.31,2090.55 1902.56,2090.55 1916.34,2076.77 1916.34,1395.67 2362.2,1395.67 2379.92,1377.95 2379.92,592.52 2750.98,592.52 2759.84,601.38 2759.84,-294.29 0,-294.29 -1.97,-292.32 -1.97,1038.39 75.79,1038.39

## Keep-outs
Keep-Out Layer:
  lines w10: -2.95,-291.34 -2.95,3175.2 -0.98,3177.17 2733.27,3177.17 2733.27,2284.45 3313.98,2284.45 3314.96,2283.46 3314.96,607.28 3311.02,603.35 2761.81,603.35 2759.84,601.38 2759.84,-294.29 2757.87,-292.32 -1.97,-292.32 -2.95,-291.34

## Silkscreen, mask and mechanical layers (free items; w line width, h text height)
Top Overlay:
  lines w10: 2734.25,3175.2 -2.95,3175.2 -2.95,-290.35 -0.98,-292.32 2753.94,-292.32 ; 2738.19,2281.5 2742.13,2285.43 3312.99,2285.43 3316.93,2281.5 3316.93,603.35 2760.83,603.35 2760.83,-287.4 ; 2738.19,2293.31 2738.19,3177.17 ; 2746.06,-292.32 2750.98,-287.4
  text "scu/i3r/wsnlab" at 1449.8,3061.02 h60
  text "powerplug by wang.w" at 1148.62,2922.24 h60
  text "2018.10.3" at 1765.75,2813.98 h60
  text "AC~OUT" at 55.12,2705.71 h30
  text "AC~IN" at 2505.91,2617.13 h30
  text "DGND" at 2288.39,-171.26 h30 r90
  text "UT2_TX" at 2187.99,-176.18 h30 r90
  text "NRST" at 2682.09,-176.18 h30 r90
  text "UT2_RX" at 2106.3,-179.13 h30 r90
  text "DIO" at 2394.69,-182.09 h30 r90
  text "CLK" at 2488.19,-183.07 h30 r90
  text "3.3v" at 2593.5,-184.06 h30 r90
